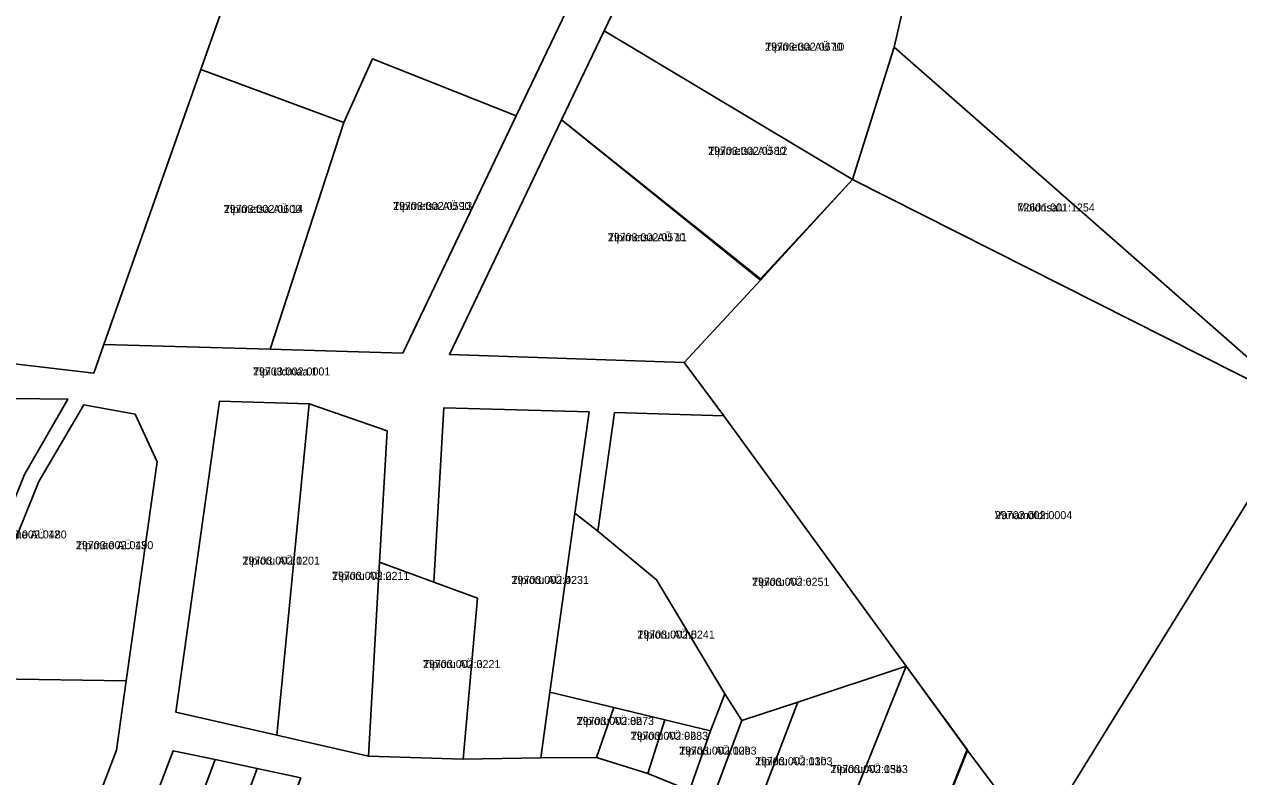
# Model space of a CAD drawing. Extents: x 504287 to 537970, y 6539941 to 6586214.
# Drawn here: x 518017.5 to 518245.2, y 6562426.2 to 6562567.1 of the extents above; entities that cross this region are included whole.
import ezdxf

# ---------------------------------------------------------------- set-up
doc = ezdxf.new("R2010")
doc.units = 0
for name, color, linetype in [('L_AADRESS', 7, 'Continuous'), ('PIIR', 7, 'Continuous'), ('TUNNUS', 7, 'Continuous')]:
    doc.layers.add(name, color=color, linetype=linetype)

msp = doc.modelspace()

# ---------------------------------------------------------------- linework, layer by layer
at = {"layer": 'PIIR'}
for points in [[(518192.21, 6562772.85), (518299.2, 6562844.83), (518335.75, 6562864.17), (518524.87, 6562904.83), (518548.12, 6562922.38), (518595.06, 6562951.11), (518629.07, 6562968.84), (518677.1, 6562981.81), (518475.75, 6562758.01), (518316.62, 6562566.33), (518257.69, 6562495.23), (518180.58, 6562562.85), (518185.96, 6562586.26), (518193.16, 6562612.47), (518199.36, 6562635.04), (518211.28, 6562678.43), (518215.15, 6562692.48), (518221.29, 6562714.82), (518225.23, 6562729.16), (518211.71, 6562770.85)], [(517811.08, 6562443.57), (517819.81, 6562456.69), (517836.55, 6562469.52), (517907.39, 6562521.29), (517948.7, 6562551.48), (517999.42, 6562593.37), (518015.61, 6562611.04), (518062.26, 6562591.54), (518050.63, 6562558.66), (518032.45, 6562507.14), (518030.55, 6562501.79), (517965.53, 6562509.41), (517922.22, 6562492.52), (517919.25, 6562445.81), (517916.74, 6562406.05), (517915.26, 6562407.19), (517906.42, 6562409.71), (517896.66, 6562413.17), (517886.39, 6562416.83), (517860.21, 6562426.13)], [(518065.02, 6562599.34), (518119.08, 6562569.51), (518109.72, 6562549.94), (518082.78, 6562560.64), (518077.41, 6562548.69), (518050.63, 6562558.66), (518062.26, 6562591.54)], [(518132.83, 6562579.75), (518185.96, 6562586.26), (518180.58, 6562562.85), (518172.76, 6562538.06), (518126.21, 6562565.89)], [(518126.21, 6562565.89), (518172.76, 6562538.06), (518155.53, 6562519.43), (518118.23, 6562549.19)], [(518257.69, 6562495.23), (518172.76, 6562538.06), (518180.58, 6562562.85)], [(518082.78, 6562560.64), (518109.72, 6562549.94), (518088.49, 6562505.53), (518063.64, 6562506.25), (518077.41, 6562548.69)], [(518050.63, 6562558.66), (518077.41, 6562548.69), (518063.64, 6562506.25), (518032.45, 6562507.14)], [(518118.23, 6562549.19), (518155.52, 6562519.19), (518141.23, 6562503.76), (518097.24, 6562505.28)], [(518257.69, 6562495.23), (518207.35, 6562413.84), (518194.31, 6562431.09), (518182.86, 6562446.88), (518148.67, 6562493.79), (518141.23, 6562503.76), (518155.52, 6562519.19), (518172.76, 6562538.06)], [(518009.88, 6562497.07), (518025.69, 6562496.93), (518017.61, 6562482.82), (518014.77, 6562475.8), (518013.86, 6562465.56), (518012.03, 6562444.56), (517996.3, 6562444.82), (517997.83, 6562480.84)], [(518028.72, 6562495.86), (518038.34, 6562494.07), (518042.44, 6562485.17), (518036.65, 6562444.14), (518012.03, 6562444.56), (518013.86, 6562465.56), (518020.3, 6562481.49)], [(518054.13, 6562496.51), (518070.96, 6562496.03), (518064.89, 6562433.97), (518045.93, 6562438.31)], [(518070.96, 6562496.03), (518085.56, 6562490.95), (518084.15, 6562466.4), (518082.06, 6562430.03), (518064.89, 6562433.97)], [(518096.2, 6562495.31), (518123.42, 6562494.52), (518120.75, 6562475.54), (518116.05, 6562442.03), (518114.35, 6562429.75), (518099.82, 6562429.48), (518102.49, 6562459.62), (518094.32, 6562462.64)], [(518148.67, 6562493.79), (518182.86, 6562446.88), (518162.54, 6562440.19), (518152.02, 6562436.73), (518148.88, 6562441.72), (518136.06, 6562463.08), (518125.05, 6562472.16), (518128.17, 6562494.39)], [(518120.75, 6562475.54), (518125.05, 6562472.16), (518136.06, 6562463.08), (518148.88, 6562441.72), (518146.17, 6562434.81), (518137.58, 6562436.87), (518128.06, 6562439.14), (518116.05, 6562442.03)], [(518084.15, 6562466.4), (518094.32, 6562462.64), (518102.49, 6562459.62), (518099.82, 6562429.48), (518082.06, 6562430.03)], [(518162.54, 6562440.19), (518182.86, 6562446.88), (518168.64, 6562411.55), (518154.43, 6562418.92)], [(518182.86, 6562446.88), (518194.26, 6562431.27), (518183.39, 6562403.9), (518168.64, 6562411.55)], [(517985.44, 6562445.14), (517996.3, 6562444.82), (518012.03, 6562444.56), (518036.65, 6562444.14), (518034.82, 6562431.2), (518022.35, 6562398.5), (517983.09, 6562416.74)], [(518116.05, 6562442.03), (518128.06, 6562439.14), (518124.82, 6562429.82), (518114.35, 6562429.75)], [(518152.02, 6562436.73), (518162.54, 6562440.19), (518154.43, 6562418.92), (518146.49, 6562421.91)], [(518128.06, 6562439.14), (518137.58, 6562436.87), (518134.4, 6562426.82), (518124.82, 6562429.82)], [(518137.58, 6562436.87), (518146.17, 6562434.81), (518142.23, 6562423.64), (518134.4, 6562426.82)], [(518045.48, 6562431.07), (518053.3, 6562429.4), (518030.03, 6562367.27), (518024.09, 6562370.04), (518022.48, 6562370.82)], [(518194.31, 6562431.09), (518207.35, 6562413.84), (518201.57, 6562394.76), (518183.39, 6562403.9)], [(518053.3, 6562429.4), (518061.21, 6562427.72), (518037.55, 6562363.76), (518030.03, 6562367.27)], [(518061.21, 6562427.72), (518069.36, 6562425.98), (518044.66, 6562360.44), (518037.55, 6562363.76)]]:
    msp.add_lwpolyline(points, close=True, dxfattribs=at)
for points in [[(518132.83, 6562579.75), (518126.21, 6562565.89), (518118.23, 6562549.19), (518097.24, 6562505.28), (518141.23, 6562503.76), (518148.67, 6562493.79), (518128.17, 6562494.39), (518125.05, 6562472.16), (518120.75, 6562475.54), (518123.42, 6562494.52), (518096.2, 6562495.31), (518094.32, 6562462.64), (518084.15, 6562466.4), (518085.56, 6562490.95), (518070.96, 6562496.03), (518054.13, 6562496.51), (518045.93, 6562438.31), (518064.89, 6562433.97), (518082.06, 6562430.03), (518099.82, 6562429.48), (518114.35, 6562429.75), (518124.82, 6562429.82), (518134.4, 6562426.82), (518142.23, 6562423.64), (518146.17, 6562434.81), (518148.88, 6562441.72), (518152.02, 6562436.73), (518146.49, 6562421.91)], [(517965.53, 6562509.41), (518030.55, 6562501.79), (518032.45, 6562507.14), (518063.64, 6562506.25), (518088.49, 6562505.53), (518109.72, 6562549.94), (518119.08, 6562569.51)], [(518014.77, 6562475.8), (518017.61, 6562482.82), (518025.69, 6562496.93), (518009.88, 6562497.07)], [(517983.09, 6562416.74), (518022.35, 6562398.5), (518034.82, 6562431.2), (518036.65, 6562444.14), (518042.44, 6562485.17), (518038.34, 6562494.07), (518028.72, 6562495.86), (518020.3, 6562481.49), (518013.86, 6562465.56)], [(518251.89, 6562177.79), (518220.42, 6562192.89), (518196.66, 6562204.18), (518176.31, 6562214.33), (518155.72, 6562224.72), (518157.51, 6562240.41), (518159.84, 6562257.7), (518161.93, 6562265.45), (518173.02, 6562300.77), (518200.21, 6562389.87), (518201.57, 6562394.76), (518207.35, 6562413.84), (518257.69, 6562495.23)], [(518069.36, 6562425.98), (518061.21, 6562427.72), (518053.3, 6562429.4), (518045.48, 6562431.07), (518022.48, 6562370.82)]]:
    msp.add_lwpolyline(points, dxfattribs=at)

# ---------------------------------------------------------------- texts
at = {"layer": 'L_AADRESS'}
for s, p in [('Tipimetsa AÜ 10', (518156.41, 6562562.16)), ('Tipimetsa AÜ 12', (518145.74, 6562542.66)), ('Tipimetsa AÜ 14', (518054.93, 6562531.78)), ('Tipimetsa AÜ 13', (518086.68, 6562532.34)), ('Möldrisalu', (518203.68, 6562532.05)), ('Tipimetsa AÜ 11', (518126.92, 6562526.48)), ('Tipi üldmaa 1', (518060.41, 6562501.34)), ('Vanamöldri', (518199.46, 6562474.44)), ('Tipimäe AÜ 12', (518010.99, 6562470.82)), ('Tipimäe AÜ 13', (518027.23, 6562468.81)), ('Tipioru AÜ 1', (518058.45, 6562465.92)), ('Tipioru AÜ 2', (518075.23, 6562463.07)), ('Tipioru AÜ 4', (518108.87, 6562462.3)), ('Tipioru AÜ 6', (518153.95, 6562461.95)), ('Tipioru AÜ 5', (518132.46, 6562452.07)), ('Tipioru AÜ 3', (518092.28, 6562446.55)), ('Tipioru AÜ 8b', (518121.07, 6562435.89)), ('Tipioru AÜ 9b', (518131.2, 6562433.11)), ('Tipioru AÜ 10b', (518140.29, 6562430.33)), ('Tipioru AÜ 11b', (518154.52, 6562428.35)), ('Tipioru AÜ 15b', (518168.64, 6562426.88))]:
    msp.add_text(s, height=1.5, dxfattribs=at).set_placement(p)
at = {"layer": 'TUNNUS'}
for s, p in [('29703:002:0670', (518156.41, 6562562.16)), ('29703:002:0580', (518145.74, 6562542.66)), ('29703:002:0600', (518054.93, 6562531.78)), ('29703:002:0590', (518086.68, 6562532.34)), ('72601:001:1254', (518203.68, 6562532.05)), ('29703:002:0570', (518126.92, 6562526.48)), ('29703:002:0001', (518060.41, 6562501.34)), ('29703:002:0004', (518199.46, 6562474.44)), ('29703:002:0480', (518010.99, 6562470.82)), ('29703:002:0490', (518027.23, 6562468.81)), ('29703:002:0201', (518058.45, 6562465.92)), ('29703:002:0211', (518075.23, 6562463.07)), ('29703:002:0231', (518108.87, 6562462.3)), ('29703:002:0251', (518153.95, 6562461.95)), ('29703:002:0241', (518132.46, 6562452.07)), ('29703:002:0221', (518092.28, 6562446.55)), ('29703:002:0273', (518121.07, 6562435.89)), ('29703:002:0283', (518131.2, 6562433.11)), ('29703:002:0293', (518140.29, 6562430.33)), ('29703:002:0303', (518154.52, 6562428.35)), ('29703:002:0343', (518168.64, 6562426.88))]:
    msp.add_text(s, height=1.5, dxfattribs=at).set_placement(p)

doc.saveas('drawing.dxf')
